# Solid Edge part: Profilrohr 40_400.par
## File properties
Username: ahadarics
Dokumentum tartalom típus: 0
Author: ahadarics
Last saved by: ahadarics
Revision: 88
Sűrűség: 0,000 kg/m^3
Pontosság: 0,990
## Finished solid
Body 1: solid body, 175 faces, 519 edges, 346 vertices.
  Faces by surface: cylinder 107, plane 68
  Edges by curve: line 305, circle 214
Bounding box of the edges (mm): 51.354 x 51.354 x 443.000, from (-25.6768, -25.6768, -409) to (25.6768, 25.6768, 34).
Cylindrical faces by radius (mm): R0.1 x16, R0.2 x30, R0.5 x28, R1 x8, R2.7 x8, R3.5 x4, R5 x4, R20 x1, R22 x8
Planar faces by outward normal: +x 6, +y 6, +z 1, -x 4, -y 4, -z 1, oblique 46
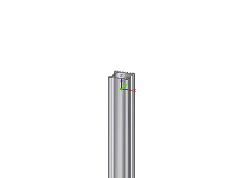
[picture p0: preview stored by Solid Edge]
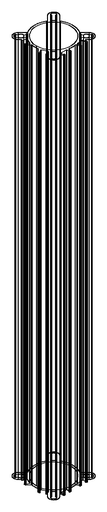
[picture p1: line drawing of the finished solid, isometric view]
